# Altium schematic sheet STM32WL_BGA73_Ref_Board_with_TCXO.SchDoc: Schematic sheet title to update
size A3; Date: Not used; ApprovedBy: Not used; CheckedBy: Not used; Author: Not used; CompanyName: STMicroelectronics; DrawnBy: Not used; Engineer: Not used; Organization: Not used; Address1: Not used; Address2: Not used; Address3: Not used; Address4: Not used; DocumentNumber: Not used; Revision: Not used; SheetNumber: 2; SheetTotal: 2
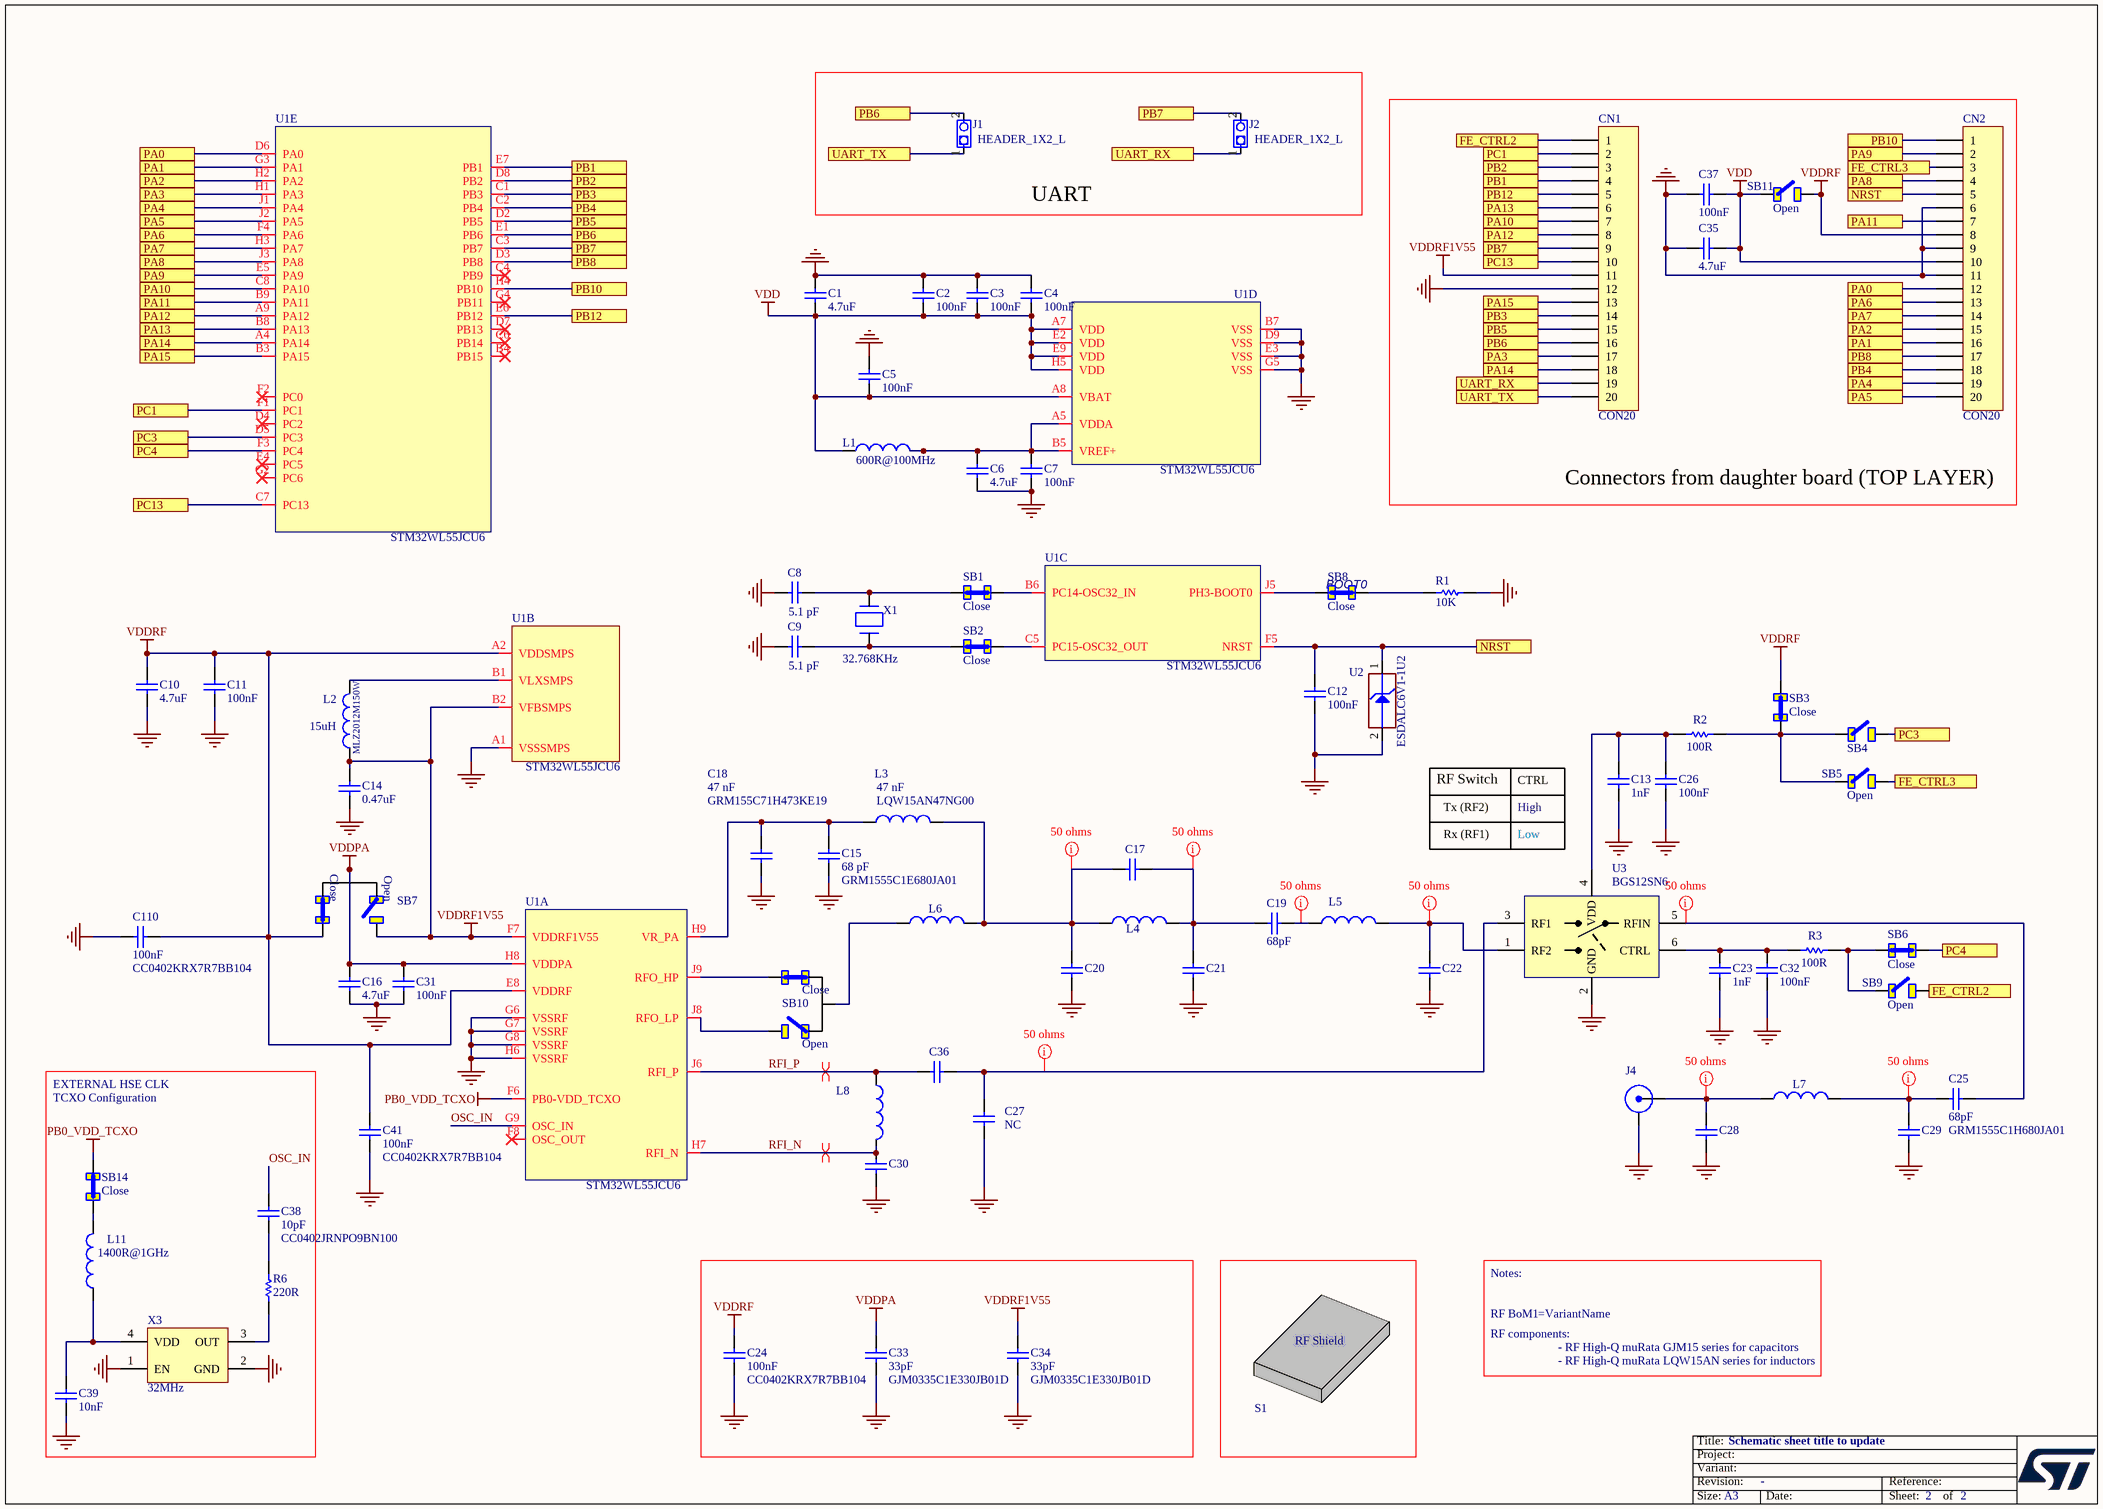
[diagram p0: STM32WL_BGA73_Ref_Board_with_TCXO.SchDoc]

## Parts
C1  value 4.7uF  [CAPC1608X09N]
C2  value 100nF  [CAPC1005X06N]
C3  value 100nF  [CAPC1005X06N]
C4  value 100nF  [CAPC1005X06N]
C5  value 100nF  [CAPC1005X06N]
C6  value 4.7uF  [CAPC1608X09N]
C7  value 100nF  [CAPC1005X06N]
C8  value 5.1 pF  [CAPC1005X06N]  (hidden comment: Capacitor)
C9  value 5.1 pF  [CAPC1005X06N]  (hidden comment: Capacitor)
C10  value 4.7uF  [CAPC1608X09N]
C11  value 100nF  [CAPC1005X06N]
C12  value 100nF  [CAPC1005X06N]
C13  value 1nF  [CAPC1005X06N]
C14  value 0.47uF  [CAPC1608X09N]
C15  value 68 pF  Manufacturer_Part_Number: GRM1555C1E680JA01  [CAPC1005X06N]
C16  value 4.7uF  [CAPC1608X09N]
C17  (no value)  [Capacitor__0402__RF]
C18  value 47 nF  Manufacturer_Part_Number: GRM155C71H473KE19  [CAPC1005X06N]
C19  value 68pF  [Capacitor__0402__RF]
C20  (no value)  [Capacitor__0402__RF]
C21  (no value)  [Capacitor__0402__RF]
C22  (no value)  [Capacitor__0402__RF]
C23  value 1nF  [CAPC1005X06N]
C24  value 100nF  Manufacturer_Part_Number: CC0402KRX7R7BB104  [CAPC1005X06N]
C25  value 68pF  Manufacturer_Part_Number: GRM1555C1H680JA01  [Capacitor__0402__RF]
C26  value 100nF  [CAPC1005X06N]
C27  NC  [Capacitor__0402__RF]
C28  (no value)  [Capacitor__0402__RF]
C29  (no value)  [Capacitor__0402__RF]
C30  (no value)  [Capacitor__0402__RF]
C31  value 100nF  [CAPC1005X06N]
C32  value 100nF  [CAPC1005X06N]
C33  value 33pF  Manufacturer_Part_Number: GJM0335C1E330JB01D  [0201]
C34  value 33pF  Manufacturer_Part_Number: GJM0335C1E330JB01D  [0201]
C35  value 4.7uF  [CAPC1608X09N]
C36  (no value)  [Capacitor__0402__RF]
C37  value 100nF  [CAPC1005X06N]
C38  value 10pF  Manufacturer_Part_Number: CC0402JRNPO9BN100  [C0402]  (hidden comment: Capacitor)
C39  value 10nF  [C0402]
C41  value 100nF  Manufacturer_Part_Number: CC0402KRX7R7BB104  [CAPC1005X06N]
C110  value 100nF  Manufacturer_Part_Number: CC0402KRX7R7BB104  [CAPC1005X06N]
CN1  CON20  [CO_SAMTEC_TSW-120-07-x-S]
CN2  CON20  [CO_SAMTEC_TSW-120-07-x-S]
J1  HEADER_1X2_L  [CO_MOLEX_22-03-2021]
J2  HEADER_1X2_L  [CO_MOLEX_22-03-2021]
J4  Amphenol_132430  [SMA_AMPHENOL_50ohms_Edge_PCB]  (value not drawn)
L1  value 600R@100MHz  [INDC1608X95N]
L2  value 15uH  Manufacturer_Part_Number: MLZ2012M150W  [INDC2012X13N]
L3  value 47 nF  Manufacturer_Part_Number: LQW15AN47NG00  [IND_MURATA_LQW15A]
L4  (no value)  [Inductor__0402__RF]
L5  (no value)  [Inductor__0402__RF]
L6  (no value)  [Inductor__0402__RF]
L7  (no value)  [Inductor__0402__RF]
L8  (no value)  [Inductor__0402__RF]
L11  value 1400R@1GHz  [IND_0402_MURATA_BLM15H_H0P5]
R1  value 10K  [RESC1608X05N]
R2  value 100R  [RESC1005X04N]
R3  value 100R  [RESC1005X04N]
R6  value 220R  [R0402]  (hidden comment: Resistor)
RF_BoM1  RF-BOM  (value not drawn)  (mechanical)
S1  RF-Shield  (value not drawn)
SB1  Close  [SB_0402]
SB2  Close  [SB_0402]
SB3  Close  [SB_0402]
SB4  Open  [SB_0402]  (value not drawn)
SB5  Open  [SB_0402]
SB6  Close  [SB_0402]
SB7  SB_3Pads  [SB3Pads_0402]  (value not drawn)
SB8  Close  [SB_0402]
SB9  Open  [SB_0402]
SB10  SB_3Pads  [SB3Pads_0402]  (value not drawn)
SB11  Open  [SB_0402]
SB14  Close  [SB_0402]
U1  Manufacturer_Part_Number: STM32WL55JCU6  [BGA73C50P9X9_500X500X60]  (parts A,B,C,D,E of 5)
U2  Manufacturer_Part_Number: ESDALC6V1-1U2  [DIOM0603X03N]
U3  BGS12SN6  [SON40P70X40-6N]
X1  value 32.768KHz  [OSC_NDK_NX2012SA]  (hidden comment: XTAL_2_PINS)
X3  value 32MHz  [CRY_NDK_NT2016SB_4P]

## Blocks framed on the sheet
UART: J1 J2
Connectors from daughter board (TOP LAYER): C35 C37 CN1 CN2 SB11

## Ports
FE_CTRL2, FE_CTRL3, NRST, PA0, PA1, PA2, PA3, PA4, PA5, PA6, PA7, PA8, PA9, PA10, PA11, PA12, PA13, PA14, PA15, PB1, PB2, PB3, PB4, PB5, PB6, PB7, PB8, PB10, PB12, PC1, PC3, PC4, PC13, UART_RX, UART_TX

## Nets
GND: C1.1 C2.1 C3.1 C4.1 C5.1 C6.2 C7.2 C8.2 C9.2 C10.2 C11.2 C12.2 C13.1 C14.2 C15.1 C16.2 C18.2 C20.2 C21.1 C22.1 C23.1 C24.2 C26.2 C27.1 C28.2 C29.2 C30.1 C31.2 C32.2 C33.1 C34.1 C35.2 C37.2 C39.1 C41.2 C110.2 CN1.12 CN2.6 CN2.9 CN2.11 J4.2(Y) R1.1 U1.A1(VSSSMPS) U1.B7(VSS) U1.D9(VSS) U1.E3(VSS) U1.G5(VSS) U1.G6(VSSRF) U1.G7(VSSRF) U1.G8(VSSRF) U1.H6(VSSRF) U2.2(GND) U3.2(GND) X3.1(EN) X3.2(GND)
PB0_VDD_TCXO: SB14.2 U1.F6(PB0-VDD_TCXO)
VDD: C1.2 C2.2 C3.2 C4.2 C5.2 C35.1 C37.1 CN2.10 L1.1 SB11.2 U1.A7(VDD) U1.A8(VBAT) U1.E2(VDD) U1.E9(VDD) U1.H5(VDD)
VDDPA: C16.1 C31.1 C33.2 SB7.2 U1.H8(VDDPA)
VDDRF: C10.1 C11.1 C24.1 C41.1 C110.1 CN2.8 SB3.1 SB7.3 SB11.1 U1.A2(VDDSMPS) U1.E8(VDDRF)
VDDRF1V55: C14.1 C34.2 CN1.11 L2.1 SB7.1 U1.B2(VFBSMPS) U1.F7(VDDRF1V55)
FE_CTRL2: CN1.1 SB9.1 ; port FE_CTRL2
FE_CTRL3: CN2.3 SB5.1 ; port FE_CTRL3
NRST: C12.1 CN2.5 U1.F5(NRST) U2.1(IO1) ; port NRST
OSC_IN: C38.2 U1.G9(OSC_IN)
PA0: CN2.12 U1.D6(PA0) ; port PA0
PA1: CN2.16 U1.G3(PA1) ; port PA1
PA2: CN2.15 U1.H2(PA2) ; port PA2
PA3: CN1.17 U1.H1(PA3) ; port PA3
PA4: CN2.19 U1.J1(PA4) ; port PA4
PA5: CN2.20 U1.J2(PA5) ; port PA5
PA6: CN2.13 U1.F4(PA6) ; port PA6
PA7: CN2.14 U1.H3(PA7) ; port PA7
PA8: CN2.4 U1.J3(PA8) ; port PA8
PA9: CN2.2 U1.E5(PA9) ; port PA9
PA10: CN1.7 U1.C8(PA10) ; port PA10
PA11: CN2.7 U1.B9(PA11) ; port PA11
PA12: CN1.8 U1.A9(PA12) ; port PA12
PA13: CN1.6 U1.B8(PA13) ; port PA13
PA14: CN1.18 U1.A4(PA14) ; port PA14
PA15: CN1.13 U1.B3(PA15) ; port PA15
PB1: CN1.4 U1.E7(PB1) ; port PB1
PB2: CN1.3 U1.D8(PB2) ; port PB2
PB3: CN1.14 U1.C1(PB3) ; port PB3
PB4: CN2.18 U1.C2(PB4) ; port PB4
PB5: CN1.15 U1.D2(PB5) ; port PB5
PB6: CN1.16 J1.2 U1.E1(PB6) ; port PB6
PB7: CN1.9 J2.2 U1.C3(PB7) ; port PB7
PB8: CN2.17 U1.D3(PB8) ; port PB8
PB10: CN2.1 U1.H4(PB10) ; port PB10
PB12: CN1.5 U1.E6(PB12) ; port PB12
PC1: CN1.2 U1.F1(PC1) ; port PC1
PC3: SB4.1 U1.D5(PC3) ; port PC3
PC4: SB6.1 U1.F3(PC4) ; port PC4
PC13: CN1.10 U1.C7(PC13) ; port PC13
RFI_N: C30.2 L8.2 U1.H7(RFI_N)
RFI_P: C36.1 L8.1 U1.J6(RFI_P)
UART_RX: CN1.19 J2.1 ; port UART_RX
UART_TX: CN1.20 J1.1 ; port UART_TX
NetC6_1: C6.1 C7.1 L1.2 U1.A5(VDDA) U1.B5(VREF+)
NetC8_1: C8.1 SB1.2 X1.2(X2)
NetC9_1: C9.1 SB2.2 X1.1(X1)
NetC13_2: C13.2 C26.1 R2.1 U3.4(VDD)
NetC15_2: C15.2 C18.1 L3.2 U1.H9(VR_PA)
NetC17_1: C17.1 C20.1 L3.1 L4.1 L6.1
NetC17_2: C17.2 C19.2 C21.2 L4.2
NetC19_1: C19.1 L5.1
NetC22_2: C22.2 L5.2 U3.1(RF2)
NetC23_2: C23.2 C32.1 R3.1 U3.6(CTRL)
NetC25_1: C25.1 U3.5(RFIN)
NetC25_2: C25.2 C29.1 L7.1
NetC27_2: C27.2 C36.2 U3.3(RF1)
NetC28_1: C28.1 J4.1(X) L7.2
NetC38_1: C38.1 R6.2
NetC39_2: C39.2 L11.1 X3.4(VDD)
NetL2_2: L2.2 U1.B1(VLXSMPS)
NetL6_2: L6.2 SB10.2
NetL11_2: L11.2 SB14.1
NetR1_2: R1.2 SB8.1
NetR2_2: R2.2 SB3.2 SB4.2 SB5.2
NetR3_2: R3.2 SB6.2 SB9.2
NetR6_1: R6.1 X3.3(OUT)
NetSB1_1: SB1.1 U1.B6(PC14-OSC32_IN)
NetSB2_1: SB2.1 U1.C5(PC15-OSC32_OUT)
NetSB8_2: SB8.2 U1.J5(PH3-BOOT0)
NetSB10_1: SB10.1 U1.J8(RFO_LP)
NetSB10_3: SB10.3 U1.J9(RFO_HP)

Not connected (* = marked no-connect by the designer): U1 B4(PB15)* C4(PB9)* C6(PB14)* D4(PC2)* D7(PB13)* E4(PC5)* F2(PC0)* F8(OSC_OUT)* G2(PC6)* G4(PB11)*

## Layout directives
differential pair: RFI_N, RFI_P
net class 50Ohms: NetC17_1, NetC17_2, NetC19_1, NetC22_2, NetC25_1, NetC25_2, NetC27_2, NetC28_1

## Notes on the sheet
- (near SB8) BOOT0
- RF Switch
- CTRL
- Tx (RF2)
- Rx (RF1)
- Low
- High
- TCXO Configuration
- EXTERNAL HSE CLK
- Notes:
- RF components:
- (near RF_BoM1) - RF High-Q muRata GJM15 series for capacitors
- (near RF_BoM1) - RF High-Q muRata LQW15AN series for inductors

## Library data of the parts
C1 C6 C10 C16 C35 = MCD-00009: Capacitor, MLCC, 4.7uF, 16V, X5R, 10%, 0603, T=0.8mm; Manufacturer_Part_Number: CC0603KRX5R7BB475; Manufacturer: YAGEO
C2-C5 C7 C11 C12 C26 C31 C32 C37 = MCD-00102: Capacitor, MLCC, 100nF, 16V, X7R, 10%, 0402, T=0,5mm; Manufacturer_Part_Number: CC0402KRX7R7BB104; Manufacturer: YAGEO
C8 C9 = MCD-00003: Capacitor, MLCC, 5.1 pF, 50V, NPO, +-0.1pF, 0402, T=0.5mm; Manufacturer_Part_Number: CC0402CRNPO9BN5R1; Manufacturer: YAGEO
C13 C23 = MCD-00198: Capacitor, MLCC, 1nF, 16V, X7R, 10%, 0402, T=0.5mm; Manufacturer_Part_Number: CC0402KRX7R7BB102; Manufacturer: YAGEO
C14 = MCD-00009: Multilayer Ceramic Capacitors MLCC - SMD/SMT 16V 0.47uF X5R 0603 10%; Manufacturer_Part_Number: CC0603KRX5R7BB474; Manufacturer: YAGEO
C15 C25 = MCD-01123: Capacitor, MLCC,68pF, 50V, C0G, 1%, 0402, T=0.5mm; Manufacturer: MURATA
C17 C22 = MCD-01123: RF Capacitor
C18 = MCD-01123: Capacitor, MLCC,47nF, 16V, X7R, 10%, 0402, T=0.5mm; Manufacturer: MURATA
C19 = MCD-01123: Capacitor, MLCC,68pF, 50V, C0G, 1%, 0402, T=0.5mm; Manufacturer_Part_Number: GRM1555C1H680JA01; Manufacturer: MURATA
C20 C28 C29 = MCD-00102: RF Capacitor
C21 = MCD-00015: RF Capacitor
C24 C41 C110 = MCD-00102: Capacitor, MLCC, 100nF, 16V, X7R, 10%, 0402, T=0,5mm; Manufacturer: YAGEO
C27 = MCD-01123: Manufacturer_Part_Number: Not Fitted
C30 C36 = MCD-01123
C33 C34 = MCD-00277: Multilayer Ceramic Capacitors MLCC - SMD/SMT 0201 33pF 25volts C0G 5%; Manufacturer: MURATA
C38 = MCD-00015: Capacitor, MLCC, 10pF, 50V, NPO, +/-5%, 0402, T=0,5mm; Part_Preference: Recommended; Manufacturer: YAGEO
C39 = MCD-00011: Capacitor, MLCC, 10nF, 16V, X7R, 10%, 0402, T=0.5mm; Manufacturer_Part_Number: CC0402KRX7R7BB103; Manufacturer: YAGEO; Provided_By: SUBCO; ECCN_US: EAR99; ECCN_EU: NEC
CN1 CN2 = CON20: Connector right-angle, pitch 2.54mm, 20 contacts; Manufacturer: SAMTEC; Manufacturer_Part_Number: TSW-120-07-L-S
J1 J2 = HEADER_1X2_L: Header 1x2 Through hole 2.54mm; Manufacturer: MOLEX
J4 = SMA_thickness_1.19mm_AMPHENOL: RF Connector, SMA End Launch Jack for 0.047 inch PCB, 50 Ohm, Flat Tab Contact; Manufacturer_Part_Number: 132430
L1 = MCD-00047: Ferrite Beads 0603 600 OHM; Manufacturer_Part_Number: BLM18AG601SN1D; Manufacturer: MURATA
L2 = MCD-01433: MLZ2012 Multilayer Shielded Inductor 15µH, ±5%; Manufacturer: TDK
L3 = MCD-01330: RF Inductor; Manufacturer: MURATA
L4-L7 = MCD-01330: RF Inductor
L8 = MCD-01330
L11 = MCD-01610: ferrite bead, 1400ohms at 1GHz, 250mA, 1.1ohms DC max; Manufacturer_Part_Number: BLM15HG102SN1#; Manufacturer: MURATA; Provided_By: SUBCO
R1 = MCD-00220: Resistor,10K,0603,1%,1/10W; Manufacturer_Part_Number: RC0603FR-0710KL; Manufacturer: YAGEO
R2 R3 = MCD-00119: Resistor,100R,0402,1%,1/16W; Manufacturer_Part_Number: RC0402FR-07100RL; Manufacturer: YAGEO
R6 = MCD-00427: Resistor,220R,0402,1%,1/16W; Manufacturer_Part_Number: RC0402FR-07220RL; Manufacturer: YAGEO; ECCN_US: EAR99; ECCN_EU: NEC; Provided_By: SUBCO
S1 = RF-Shield: RF Shield Frame + Cover without apertures; Manufacturer: Masach Tech; Manufacturer_Part_Number: MS409-10
SB1 SB2 SB8 = SB_0Ohm: Solder Bridge 0R [0402] (Populated with 0 Ohm); Manufacturer: Vishay / Dale; Manufacturer_Part_Number: RCS04020000Z0ED
SB3 = SB_0Ohm: Solder Bridge 0R [0402] (Populated with 0 ohm); Manufacturer: Vishay / Dale; Manufacturer_Part_Number: RCS04020000Z0ED
SB4 = SB_Open: Solder Bridge Open [0402] (Unpopulated); Manufacturer: NOT FITTED
SB5 SB9 SB11 = SB_Open: Solder Bridge Open [0402] (Unpopulated)
SB6 = SB_0Ohm: Solder Bridge 0R [0402] (Populated with 0 ohm); Manufacturer: Vishay / Dale; Manufacturer_Part_Number: RCS04020000Z0ED; VALUE: 0
SB7 SB10 = SB_3Pads: Solder Bridge Open [0402] (Unpopulated); Manufacturer: NOT FITTED
SB14 = SB_0Ohm: Solder Bridge 0R [0402] (Populated with 0 Ohm); Manufacturer: Vishay / Dale; Manufacturer_Part_Number: RCS04020000Z0ED; VALUE: 0
U1 = MCD-01435: Multiprotocol Wireless 32-bit MCUwith LPWAN Sub-GHz radio solution; Manufacturer: STMICROELECTRONICS
U2 = MCD-00170: ESD protection 6V1; Manufacturer: STMICROELECTRONICS
U3 = BGS12SN6: DC switch - Ultra-Low  SPDT analog switch; Manufacturer: INFINEON
X1 = MCD-01479: Crystal 32.768kHz, 6pF, -+20PPM, R=80K, SMD; Manufacturer_Part_Number: NX2012SA 32.768KHz EXS00A-MU00527; Manufacturer: NDK
X3 = MCD-01492: NT2016SA-32M-END4263A; Part_Type: Crystal_Osc; Manufacturer: NDK; Provided_By: SUBCO; ECCN_US: EAR99; ECCN_EU: NEC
